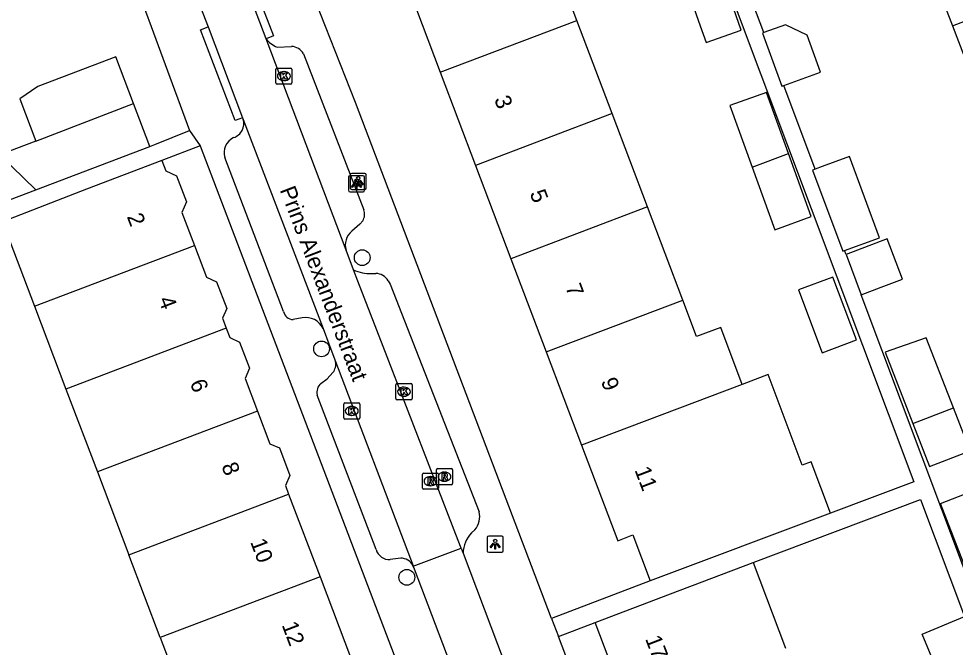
# Model space of a CAD drawing. Extents: x 159961 to 160856, y 382704 to 383353.
# Drawn here: x 160398.7 to 160456.8, y 383033.8 to 383072.7 of the extents above; entities that cross this region are included whole.
import ezdxf

# ---------------------------------------------------------------- set-up
doc = ezdxf.new("R2010")
doc.units = 0
for name, color, linetype in [('IMGEO_Boom', 7, 'Continuous'), ('IMGEO_Kolk', 7, 'Continuous'), ('IMGEO_Lichtpunt', 7, 'Continuous'), ('IMGEO_Openbare_ruimte_label', 7, 'Continuous'), ('IMGEO_Pand', 7, 'Continuous'), ('IMGEO_Pand_nummerreeks', 7, 'Continuous'), ('IMGEO_Rijbaan_lokaal_open', 7, 'Continuous'), ('IMGEO_Rioolput', 7, 'Continuous'), ('IMGEO_Voetpad_open', 7, 'Continuous')]:
    doc.layers.add(name, color=color, linetype=linetype)

msp = doc.modelspace()

# ---------------------------------------------------------------- linework, layer by layer
at = {"layer": 'IMGEO_Boom'}
for centre in [(160420.041, 383057.918), (160417.519, 383052.264), (160422.805, 383038.108)]:
    msp.add_circle(centre, 0.489, dxfattribs=at)
at = {"layer": 'IMGEO_Kolk'}
for p, q in [((160414.68, 383068.742), (160414.68, 383069.594)), ((160414.755, 383069.668), (160415.607, 383069.668)), ((160415.168, 383069.448), (160415.193, 383069.448)), ((160415.681, 383069.594), (160415.681, 383068.742)), ((160415.191, 383068.888), (160415.166, 383068.888)), ((160415.607, 383068.668), (160414.755, 383068.668)), ((160422.127, 383049.186), (160422.127, 383050.038)), ((160422.202, 383050.112), (160423.054, 383050.112)), ((160422.615, 383049.892), (160422.64, 383049.892)), ((160423.128, 383050.038), (160423.128, 383049.186)), ((160423.054, 383049.112), (160422.202, 383049.112)), ((160422.638, 383049.332), (160422.613, 383049.332)), ((160418.889, 383047.992), (160418.889, 383048.844)), ((160418.964, 383048.918), (160419.816, 383048.918)), ((160419.377, 383048.698), (160419.402, 383048.698)), ((160419.89, 383048.844), (160419.89, 383047.992)), ((160419.816, 383047.918), (160418.964, 383047.918)), ((160419.4, 383048.138), (160419.375, 383048.138))]:
    msp.add_line(p, q, dxfattribs=at)
for points in [[(160414.68, 383068.742), (160414.68, 383069.594)], [(160414.755, 383069.668), (160415.607, 383069.668)], [(160415.681, 383069.594), (160415.681, 383068.742)], [(160415.001, 383069.368), (160415.124, 383069.368), (160415.124, 383069.217), (160415.254, 383069.368), (160415.418, 383069.368), (160415.272, 383069.217), (160415.425, 383068.968), (160415.273, 383068.968), (160415.188, 383069.132), (160415.124, 383069.065), (160415.124, 383068.968), (160415.001, 383068.968), (160415.001, 383069.368)], [(160415.607, 383068.668), (160414.755, 383068.668)], [(160422.127, 383049.186), (160422.127, 383050.038)], [(160422.202, 383050.112), (160423.054, 383050.112)], [(160422.448, 383049.812), (160422.571, 383049.812), (160422.571, 383049.661), (160422.701, 383049.812), (160422.865, 383049.812), (160422.719, 383049.661), (160422.872, 383049.412), (160422.72, 383049.412), (160422.635, 383049.576), (160422.571, 383049.509), (160422.571, 383049.412), (160422.448, 383049.412), (160422.448, 383049.812)], [(160423.128, 383050.038), (160423.128, 383049.186)], [(160423.054, 383049.112), (160422.202, 383049.112)], [(160418.889, 383047.992), (160418.889, 383048.844)], [(160418.964, 383048.918), (160419.816, 383048.918)], [(160419.21, 383048.618), (160419.333, 383048.618), (160419.333, 383048.467), (160419.463, 383048.618), (160419.627, 383048.618), (160419.481, 383048.467), (160419.634, 383048.218), (160419.482, 383048.218), (160419.397, 383048.382), (160419.333, 383048.315), (160419.333, 383048.218), (160419.21, 383048.218), (160419.21, 383048.618)], [(160419.89, 383048.844), (160419.89, 383047.992)], [(160419.816, 383047.918), (160418.964, 383047.918)]]:
    msp.add_lwpolyline(points, dxfattribs=at)
for centre, start, end in [((160414.757, 383069.592), 91.55205, 178.44795), ((160414.757, 383069.592), 91.55205, 178.44795), ((160415.605, 383069.592), 1.55205, 88.44795), ((160415.605, 383069.592), 1.55205, 88.44795), ((160414.757, 383068.744), 181.55205, 268.44795), ((160414.757, 383068.744), 181.55205, 268.44795), ((160415.605, 383068.744), 271.55205, 358.44795), ((160415.605, 383068.744), 271.55205, 358.44795), ((160422.204, 383050.036), 91.55205, 178.44795), ((160422.204, 383050.036), 91.55205, 178.44795), ((160423.052, 383050.036), 1.55205, 88.44795), ((160423.052, 383050.036), 1.55205, 88.44795), ((160422.204, 383049.188), 181.55205, 268.44795), ((160422.204, 383049.188), 181.55205, 268.44795), ((160423.052, 383049.188), 271.55205, 358.44795), ((160423.052, 383049.188), 271.55205, 358.44795), ((160418.966, 383048.842), 91.55205, 178.44795), ((160418.966, 383048.842), 91.55205, 178.44795), ((160419.814, 383048.842), 1.55205, 88.44795), ((160419.814, 383048.842), 1.55205, 88.44795), ((160418.966, 383047.994), 181.55205, 268.44795), ((160418.966, 383047.994), 181.55205, 268.44795), ((160419.814, 383047.994), 271.55205, 358.44795), ((160419.814, 383047.994), 271.55205, 358.44795)]:
    msp.add_arc(centre, 0.0765, start, end, dxfattribs=at)
for centre, major_axis, ratio, start_param, end_param in [((160415.167, 383069.168), (-0.387, 0.002), 0.722429, 4.712389, 7.853982), ((160415.192, 383069.168), (-0.39, 0.002), 0.717154, 1.570796, 4.712389), ((160422.614, 383049.612), (-0.387, 0.002), 0.722429, 4.712389, 7.853982), ((160422.639, 383049.612), (-0.39, 0.002), 0.717154, 1.570796, 4.712389), ((160419.376, 383048.418), (-0.387, 0.002), 0.722429, 4.712389, 7.853982), ((160419.401, 383048.418), (-0.39, 0.002), 0.717154, 1.570796, 4.712389)]:
    msp.add_ellipse(centre, major_axis=major_axis, ratio=ratio, start_param=start_param, end_param=end_param, dxfattribs=at)
at = {"layer": 'IMGEO_Lichtpunt'}
for p, q in [((160420.092, 383062.992), (160419.284, 383062.992)), ((160420.092, 383062.992), (160419.284, 383062.992)), ((160419.294, 383063.046), (160419.294, 383062.239)), ((160419.294, 383063.046), (160419.294, 383062.239)), ((160420.196, 383063.141), (160419.388, 383063.141)), ((160420.196, 383063.141), (160419.388, 383063.141)), ((160420.29, 383062.239), (160420.29, 383063.046)), ((160420.29, 383062.239), (160420.29, 383063.046)), ((160419.19, 383062.897), (160419.19, 383062.09)), ((160419.19, 383062.897), (160419.19, 383062.09)), ((160420.186, 383062.09), (160420.186, 383062.897)), ((160420.186, 383062.09), (160420.186, 383062.897)), ((160419.284, 383061.996), (160420.092, 383061.996)), ((160419.284, 383061.996), (160420.092, 383061.996)), ((160419.388, 383062.145), (160420.196, 383062.145)), ((160419.388, 383062.145), (160420.196, 383062.145)), ((160427.787, 383040.568), (160427.787, 383039.761)), ((160427.787, 383040.568), (160427.787, 383039.761)), ((160428.689, 383040.663), (160427.881, 383040.663)), ((160428.689, 383040.663), (160427.881, 383040.663)), ((160428.783, 383039.761), (160428.783, 383040.568)), ((160428.783, 383039.761), (160428.783, 383040.568)), ((160427.881, 383039.667), (160428.689, 383039.667)), ((160427.881, 383039.667), (160428.689, 383039.667))]:
    msp.add_line(p, q, dxfattribs=at)
for points in [[(160419.564, 383062.561), (160419.603, 383062.533), (160419.415, 383062.271), (160419.377, 383062.298), (160419.564, 383062.561)], [(160419.668, 383062.71), (160419.707, 383062.682), (160419.519, 383062.42), (160419.481, 383062.447), (160419.668, 383062.71)], [(160419.666, 383062.513), (160419.713, 383062.513), (160419.713, 383062.191), (160419.666, 383062.191), (160419.666, 383062.513)], [(160419.77, 383062.662), (160419.817, 383062.662), (160419.817, 383062.34), (160419.77, 383062.34), (160419.77, 383062.662)], [(160419.776, 383062.533), (160419.814, 383062.56), (160420.001, 383062.298), (160419.962, 383062.27), (160419.776, 383062.533)], [(160419.88, 383062.682), (160419.918, 383062.709), (160420.105, 383062.447), (160420.066, 383062.419), (160419.88, 383062.682)], [(160428.161, 383040.232), (160428.2, 383040.204), (160428.012, 383039.942), (160427.974, 383039.969), (160428.161, 383040.232)], [(160428.263, 383040.184), (160428.31, 383040.184), (160428.31, 383039.862), (160428.263, 383039.862), (160428.263, 383040.184)], [(160428.373, 383040.204), (160428.411, 383040.231), (160428.598, 383039.969), (160428.559, 383039.941), (160428.373, 383040.204)]]:
    msp.add_lwpolyline(points, dxfattribs=at)
for centre in [(160419.689, 383062.695), (160419.793, 383062.844), (160428.286, 383040.366)]:
    msp.add_circle(centre, 0.0994, dxfattribs=at)
for centre, start, end in [((160419.284, 383062.897), 90, 180), ((160419.284, 383062.897), 90, 180), ((160419.388, 383063.046), 90, 180), ((160419.388, 383063.046), 90, 180), ((160420.092, 383062.897), 0, 90), ((160420.092, 383062.897), 0, 90), ((160420.196, 383063.046), 0, 90), ((160420.196, 383063.046), 0, 90), ((160419.284, 383062.09), 180, 270), ((160419.284, 383062.09), 180, 270), ((160419.388, 383062.239), 180, 270), ((160419.388, 383062.239), 180, 270), ((160420.092, 383062.09), 270, 0), ((160420.092, 383062.09), 270, 360), ((160420.196, 383062.239), 270, 0), ((160420.196, 383062.239), 270, 360), ((160427.881, 383040.568), 90, 180), ((160427.881, 383040.568), 90, 180), ((160428.689, 383040.568), 0, 90), ((160428.689, 383040.568), 0, 90), ((160427.881, 383039.761), 180, 270), ((160427.881, 383039.761), 180, 270), ((160428.689, 383039.761), 270, 0), ((160428.689, 383039.761), 270, 360)]:
    msp.add_arc(centre, 0.0946, start, end, dxfattribs=at)
at = {"layer": 'IMGEO_Pand'}
for points in [[(160433.344, 383072.618), (160431.088, 383078.572), (160427.311, 383077.102), (160422.635, 383075.33), (160424.878, 383069.41)], [(160454.677, 383077.379), (160456.628, 383072.287)], [(160439.969, 383075.245), (160440.996, 383072.284), (160441.355, 383071.247), (160443.542, 383072.006), (160442.156, 383076.003), (160439.969, 383075.245)], [(160456.628, 383072.287), (160466.221, 383075.973)], [(160424.878, 383069.41), (160433.344, 383072.618)], [(160435.534, 383066.84), (160433.344, 383072.618)], [(160446.184, 383068.586), (160448.453, 383069.409), (160447.62, 383071.707), (160446.284, 383072.353), (160444.95, 383071.869)], [(160456.628, 383072.287), (160458.596, 383067.151)], [(160444.95, 383071.869), (160444.858, 383071.836), (160446.052, 383068.538), (160446.184, 383068.586)], [(160405.86, 383067.459), (160404.757, 383070.355), (160399.931, 383068.516), (160398.8, 383067.75), (160399.792, 383065.145)], [(160424.878, 383069.41), (160427.067, 383063.632)], [(160446.467, 383064.375), (160445.097, 383068.158), (160442.832, 383067.337), (160444.215, 383063.522)], [(160399.792, 383065.145), (160405.86, 383067.459)], [(160406.87, 383064.808), (160405.86, 383067.459)], [(160435.534, 383066.84), (160427.067, 383063.632)], [(160437.723, 383061.062), (160435.534, 383066.84)], [(160399.792, 383065.145), (160397.557, 383064.292), (160399.802, 383062.116)], [(160399.802, 383062.116), (160406.87, 383064.808)], [(160444.215, 383063.522), (160446.467, 383064.375)], [(160444.215, 383063.522), (160445.618, 383059.648), (160447.883, 383060.469), (160446.467, 383064.375)], [(160449.949, 383058.361), (160452.102, 383059.152), (160450.25, 383064.183), (160448.561, 383063.562), (160448.122, 383063.401)], [(160407.622, 383063.941), (160402.95, 383062.16), (160397.726, 383060.145)], [(160407.622, 383063.941), (160407.871, 383063.287), (160408.529, 383062.992), (160409.144, 383061.377), (160408.849, 383060.717), (160409.631, 383058.666)], [(160427.067, 383063.632), (160429.257, 383057.854)], [(160448.122, 383063.401), (160447.959, 383063.341), (160449.842, 383058.322), (160449.949, 383058.361)], [(160437.723, 383061.062), (160429.257, 383057.854)], [(160439.913, 383055.284), (160437.723, 383061.062)], [(160397.726, 383060.145), (160399.717, 383054.904)], [(160450.985, 383055.613), (160452.223, 383056.079), (160453.539, 383056.575), (160452.597, 383059.076), (160450.042, 383058.114)], [(160399.717, 383054.904), (160409.631, 383058.666)], [(160409.631, 383058.666), (160410.38, 383056.699), (160411.011, 383056.416), (160411.636, 383054.774), (160411.367, 383054.173), (160411.607, 383053.543)], [(160429.257, 383057.854), (160431.446, 383052.075)], [(160450.042, 383058.114), (160450.985, 383055.613)], [(160447.089, 383055.914), (160448.553, 383052.028), (160450.684, 383052.831), (160449.22, 383056.716), (160447.089, 383055.914)], [(160399.717, 383054.904), (160401.667, 383049.772)], [(160431.446, 383052.075), (160439.913, 383055.284)], [(160443.59, 383050.065), (160442.265, 383053.59), (160440.768, 383053.027), (160439.913, 383055.284)], [(160411.607, 383053.543), (160401.667, 383049.772)], [(160411.607, 383053.543), (160411.83, 383052.96), (160412.435, 383052.688), (160413.054, 383051.063), (160412.774, 383050.438), (160413.548, 383048.407)], [(160456.695, 383048.602), (160455.009, 383052.95), (160452.466, 383052.069), (160454.184, 383047.636)], [(160431.446, 383052.075), (160433.635, 383046.298)], [(160449.073, 383042.09), (160447.88, 383045.265), (160447.322, 383045.055), (160445.21, 383050.674), (160443.59, 383050.065)], [(160401.667, 383049.772), (160403.617, 383044.639)], [(160443.59, 383050.065), (160433.635, 383046.298)], [(160454.184, 383047.636), (160456.695, 383048.602)], [(160454.184, 383047.636), (160455.216, 383044.971), (160457.725, 383045.943), (160456.695, 383048.602)], [(160413.548, 383048.407), (160403.617, 383044.639)], [(160413.548, 383048.407), (160414.316, 383046.391), (160414.906, 383046.127), (160415.555, 383044.423), (160415.272, 383043.792), (160415.473, 383043.264)], [(160433.635, 383046.298), (160435.878, 383040.379), (160436.813, 383040.733), (160437.883, 383037.885)], [(160403.617, 383044.639), (160405.567, 383039.506)], [(160458.861, 383043.841), (160460.684, 383039.136), (160457.721, 383037.987), (160455.897, 383042.693), (160458.861, 383043.841)], [(160405.567, 383039.506), (160415.473, 383043.264)], [(160415.473, 383043.264), (160417.429, 383038.133)], [(160449.073, 383042.09), (160437.883, 383037.885)], [(160407.518, 383034.373), (160405.567, 383039.506)], [(160434.483, 383035.317), (160439.159, 383037.089), (160444.278, 383039.029)], [(160444.278, 383039.029), (160446.289, 383033.722)], [(160417.429, 383038.133), (160407.518, 383034.373)], [(160417.429, 383038.133), (160419.384, 383033.002)], [(160436.509, 383029.97), (160434.483, 383035.317)], [(160458.648, 383032.655), (160456.013, 383031.557), (160454.75, 383034.59), (160457.385, 383035.688)], [(160407.518, 383034.373), (160409.468, 383029.24)]]:
    msp.add_lwpolyline(points, dxfattribs=at)
at = {"layer": 'IMGEO_Rijbaan_lokaal_open'}
for points in [[(160414.077, 383071.485), (160412.742, 383075.024)], [(160409.728, 383074.203), (160410.485, 383072.21)], [(160410.485, 383072.21), (160412.619, 383066.586)], [(160419.041, 383058.375), (160414.077, 383071.485)], [(160412.619, 383066.586), (160412.657, 383066.487)], [(160412.657, 383066.487), (160417.616, 383053.519)], [(160419.498, 383057.168), (160419.041, 383058.375)], [(160426.171, 383039.923), (160425.991, 383040.387), (160421.337, 383052.404), (160419.77, 383056.451), (160419.498, 383057.168)], [(160417.616, 383053.519), (160417.972, 383052.57), (160418.386, 383051.479)], [(160418.386, 383051.479), (160423.026, 383039.266), (160423.192, 383038.831)], [(160423.203, 383038.801), (160426.171, 383039.923)], [(160426.171, 383039.923), (160426.24, 383039.744), (160426.294, 383039.601)], [(160426.294, 383039.601), (160430.975, 383027.226)], [(160423.192, 383038.831), (160423.203, 383038.801)], [(160428.104, 383025.934), (160423.277, 383038.606), (160423.203, 383038.801)]]:
    msp.add_lwpolyline(points, dxfattribs=at)
at = {"layer": 'IMGEO_Rioolput'}
for p, q in [((160423.773, 383043.643), (160423.773, 383044.495)), ((160423.848, 383044.569), (160424.7, 383044.569)), ((160424.638, 383043.922), (160424.638, 383044.774)), ((160424.713, 383044.848), (160425.565, 383044.848)), ((160424.774, 383044.495), (160424.774, 383043.643)), ((160425.126, 383044.628), (160425.151, 383044.628)), ((160425.639, 383044.774), (160425.639, 383043.922)), ((160424.261, 383044.349), (160424.286, 383044.349)), ((160425.565, 383043.848), (160424.713, 383043.848)), ((160425.149, 383044.068), (160425.124, 383044.068)), ((160424.7, 383043.569), (160423.848, 383043.569)), ((160424.284, 383043.789), (160424.259, 383043.789))]:
    msp.add_line(p, q, dxfattribs=at)
for points in [[(160423.773, 383043.643), (160423.773, 383044.495)], [(160423.848, 383044.569), (160424.7, 383044.569)], [(160424.638, 383043.922), (160424.638, 383044.774)], [(160424.713, 383044.848), (160425.565, 383044.848)], [(160424.774, 383044.495), (160424.774, 383043.643)], [(160425.227, 383044.546), (160424.975, 383044.548), (160424.975, 383044.148)], [(160425.153, 383044.467), (160425.099, 383044.467), (160425.099, 383044.386)], [(160425.639, 383044.774), (160425.639, 383043.922)], [(160424.362, 383044.267), (160424.11, 383044.269), (160424.11, 383043.869)], [(160424.11, 383043.869), (160424.234, 383043.869), (160424.234, 383044.031), (160424.245, 383044.031)], [(160424.288, 383044.188), (160424.234, 383044.188), (160424.234, 383044.107)], [(160424.234, 383044.107), (160424.286, 383044.107)], [(160424.292, 383044.002), (160424.363, 383043.869), (160424.503, 383043.869), (160424.438, 383043.995)], [(160425.565, 383043.848), (160424.713, 383043.848)], [(160424.975, 383044.148), (160425.099, 383044.148), (160425.099, 383044.31), (160425.11, 383044.31)], [(160425.099, 383044.386), (160425.151, 383044.386)], [(160425.157, 383044.281), (160425.228, 383044.148), (160425.368, 383044.148), (160425.303, 383044.274)], [(160424.7, 383043.569), (160423.848, 383043.569)]]:
    msp.add_lwpolyline(points, dxfattribs=at)
for centre, radius, start, end in [((160423.85, 383044.493), 0.0765, 91.55205, 178.44795), ((160423.85, 383044.493), 0.0765, 91.55205, 178.44795), ((160424.715, 383044.772), 0.0765, 91.55205, 178.44795), ((160424.715, 383044.772), 0.0765, 91.55205, 178.44795), ((160424.698, 383044.493), 0.0765, 1.55205, 88.44795), ((160424.698, 383044.493), 0.0765, 1.55205, 88.44795), ((160425.159, 383044.371), 0.0964, 77.00612, 93.18647), ((160425.173, 383044.428), 0.0378, 276.66336, 79.67722), ((160425.226, 383044.436), 0.109, 350.36119, 89.41601), ((160425.224, 383044.436), 0.112, 277.58423, 350.98172), ((160425.563, 383044.772), 0.0765, 1.55205, 88.44795), ((160425.563, 383044.772), 0.0765, 1.55205, 88.44795), ((160424.244, 383043.978), 0.0533, 26.02933, 88.69889), ((160424.27, 383044.296), 0.19, 274.7715, 282.96867), ((160424.294, 383044.092), 0.0964, 77.00612, 93.18647), ((160424.308, 383044.149), 0.0378, 276.66336, 79.67722), ((160424.361, 383044.157), 0.109, 350.36119, 89.41601), ((160424.359, 383044.157), 0.112, 277.58423, 350.98172), ((160424.343, 383043.942), 0.108, 29.51342, 73.79051), ((160424.715, 383043.924), 0.0765, 181.55205, 268.44795), ((160424.715, 383043.924), 0.0765, 181.55205, 268.44795), ((160425.109, 383044.257), 0.0533, 26.02933, 88.69889), ((160425.135, 383044.575), 0.19, 274.7715, 282.96867), ((160425.208, 383044.221), 0.108, 29.51342, 73.79051), ((160425.563, 383043.924), 0.0765, 271.55205, 358.44795), ((160425.563, 383043.924), 0.0765, 271.55205, 358.44795), ((160423.85, 383043.645), 0.0765, 181.55205, 268.44795), ((160423.85, 383043.645), 0.0765, 181.55205, 268.44795), ((160424.698, 383043.645), 0.0765, 271.55205, 358.44795), ((160424.698, 383043.645), 0.0765, 271.55205, 358.44795)]:
    msp.add_arc(centre, radius, start, end, dxfattribs=at)
for centre, major_axis, ratio, start_param, end_param in [((160425.125, 383044.348), (-0.387, 0.002), 0.722429, 4.712389, 7.853982), ((160425.15, 383044.348), (-0.39, 0.002), 0.717154, 1.570796, 4.712389), ((160424.26, 383044.069), (-0.387, 0.002), 0.722429, 4.712389, 7.853982), ((160424.285, 383044.069), (-0.39, 0.002), 0.717154, 1.570796, 4.712389)]:
    msp.add_ellipse(centre, major_axis=major_axis, ratio=ratio, start_param=start_param, end_param=end_param, dxfattribs=at)
at = {"layer": 'IMGEO_Voetpad_open'}
for points in [[(160431.776, 383035.564), (160419.63, 383067.53), (160415.599, 383077.746), (160414.428, 383080.713), (160411.87, 383087.197), (160407.676, 383096.869), (160407.237, 383099.321)], [(160436.385, 383094.185), (160435.282, 383093.776), (160438.937, 383084.582), (160439.971, 383081.99), (160454.246, 383044.035), (160449.073, 383042.09)], [(160397.167, 383086.9), (160404.22, 383079.65), (160409.328, 383065.794)], [(160412.742, 383075.024), (160413.183, 383075.194), (160414.543, 383071.664), (160414.077, 383071.485)], [(160444.95, 383071.869), (160444.262, 383073.665)], [(160412.619, 383066.586), (160412.152, 383066.409), (160410.021, 383072.034), (160410.485, 383072.21)], [(160414.755, 383070.964), (160415.657, 383071.004)], [(160416.389, 383070.541), (160420.13, 383060.878)], [(160448.122, 383063.401), (160446.184, 383068.586)], [(160406.87, 383064.808), (160407.184, 383064.928), (160409.328, 383065.794)], [(160409.328, 383065.794), (160410.001, 383064.837)], [(160410.001, 383064.837), (160407.622, 383063.941)], [(160410.001, 383064.837), (160434.709, 383000), (160437.48, 382992.728)], [(160415.158, 383054.58), (160411.512, 383064.114)], [(160387.545, 383057.271), (160389.324, 383057.947), (160389.183, 383058.085), (160399.802, 383062.116)], [(160420.068, 383060.206), (160419.887, 383059.986), (160419.404, 383059.551)], [(160450.042, 383058.114), (160449.949, 383058.361)], [(160420.625, 383056.929), (160420.878, 383056.932)], [(160421.653, 383056.485), (160421.774, 383056.282), (160427.292, 383042.176)], [(160470.41, 383036.318), (160462.384, 383033.361), (160460.386, 383032.514), (160459.766, 383032.251), (160450.985, 383055.613)], [(160416.307, 383054.185), (160415.754, 383054.081)], [(160417.473, 383050.123), (160417.863, 383050.412), (160418.217, 383050.794)], [(160420.895, 383039.829), (160417.24, 383049.401)], [(160444.278, 383039.029), (160454.66, 383042.934), (160457.385, 383035.688)], [(160427.026, 383041.053), (160426.812, 383040.867)], [(160422.426, 383039.293), (160421.779, 383039.211)], [(160437.883, 383037.885), (160431.776, 383035.564)], [(160431.776, 383035.564), (160432.2, 383034.449)], [(160432.2, 383034.449), (160434.483, 383035.317)], [(160447.085, 382996.244), (160445.289, 383000), (160432.2, 383034.449)]]:
    msp.add_lwpolyline(points, dxfattribs=at)
for centre, radius, start, end in [((160415.345, 383072.433), 1.583, 216.79626, 248.12375), ((160415.625, 383070.143), 0.862, 27.52109, 87.85109), ((160411.803, 383066.218), 0.896, 287.16658, 17.48439), ((160412.551, 383064.399), 1.077, 116.69164, 195.35782), ((160419.493, 383060.598), 0.696, 325.74027, 23.71714), ((160420.055, 383058.706), 1.067, 127.62073, 198.07113), ((160420.521, 383059.216), 2.29, 243.45529, 272.59834), ((160420.889, 383056.056), 0.876, 29.31173, 90.73779), ((160415.783, 383054.721), 0.641, 192.74067, 267.38394), ((160416.534, 383053.013), 1.194, 25.08894, 100.97841), ((160417.552, 383051.321), 0.849, 321.58869, 10.69335), ((160417.978, 383049.561), 0.755, 131.96351, 192.26519), ((160426.053, 383041.877), 1.275, 319.76743, 13.58097), ((160428.291, 383039.523), 1.999, 137.73605, 177.75886), ((160421.737, 383040.092), 0.882, 197.35869, 272.7269), ((160422.451, 383038.469), 0.824, 26.04693, 91.76193)]:
    msp.add_arc(centre, radius, start, end, dxfattribs=at)

# ---------------------------------------------------------------- texts
at = {"layer": 'IMGEO_Openbare_ruimte_label'}
msp.add_text('Prins Alexanderstraat', height=1, rotation=290.9182, dxfattribs=at).set_placement((160414.913, 383062.119))
at = {"layer": 'IMGEO_Pand_nummerreeks'}
for s, rotation, p in [('3', 290.75179, (160428.205, 383067.743)), ('5', 290.75179, (160430.412, 383061.918)), ('2', 290.78186, (160405.434, 383060.464)), ('7', 290.75179, (160432.619, 383056.092)), ('4', 290.78186, (160407.388, 383055.315)), ('6', 290.78186, (160409.341, 383050.168)), ('9', 290.75179, (160434.826, 383050.267)), ('8', 290.78186, (160411.296, 383045.017)), ('11', 290.75179, (160436.911, 383044.765)), ('10', 290.78186, (160413.085, 383040.302)), ('12', 290.78186, (160415.036, 383035.16)), ('17', 290.99166, (160437.571, 383034.303))]:
    msp.add_text(s, height=1, rotation=rotation, dxfattribs=at).set_placement(p)

doc.saveas('drawing.dxf')
